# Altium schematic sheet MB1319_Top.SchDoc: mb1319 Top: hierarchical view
size A4; Date: Not used; ApprovedBy: Not used; CheckedBy: Not used; Author: Not used; CompanyName: STMicroelectronics; DrawnBy: Not used; Engineer: Not used; Organization: Not used; Address1: Not used; Address2: Not used; Address3: Not used; Address4: Not used; DocumentNumber: 2; Revision: A-01-P3; SheetNumber: 2; SheetTotal: 8
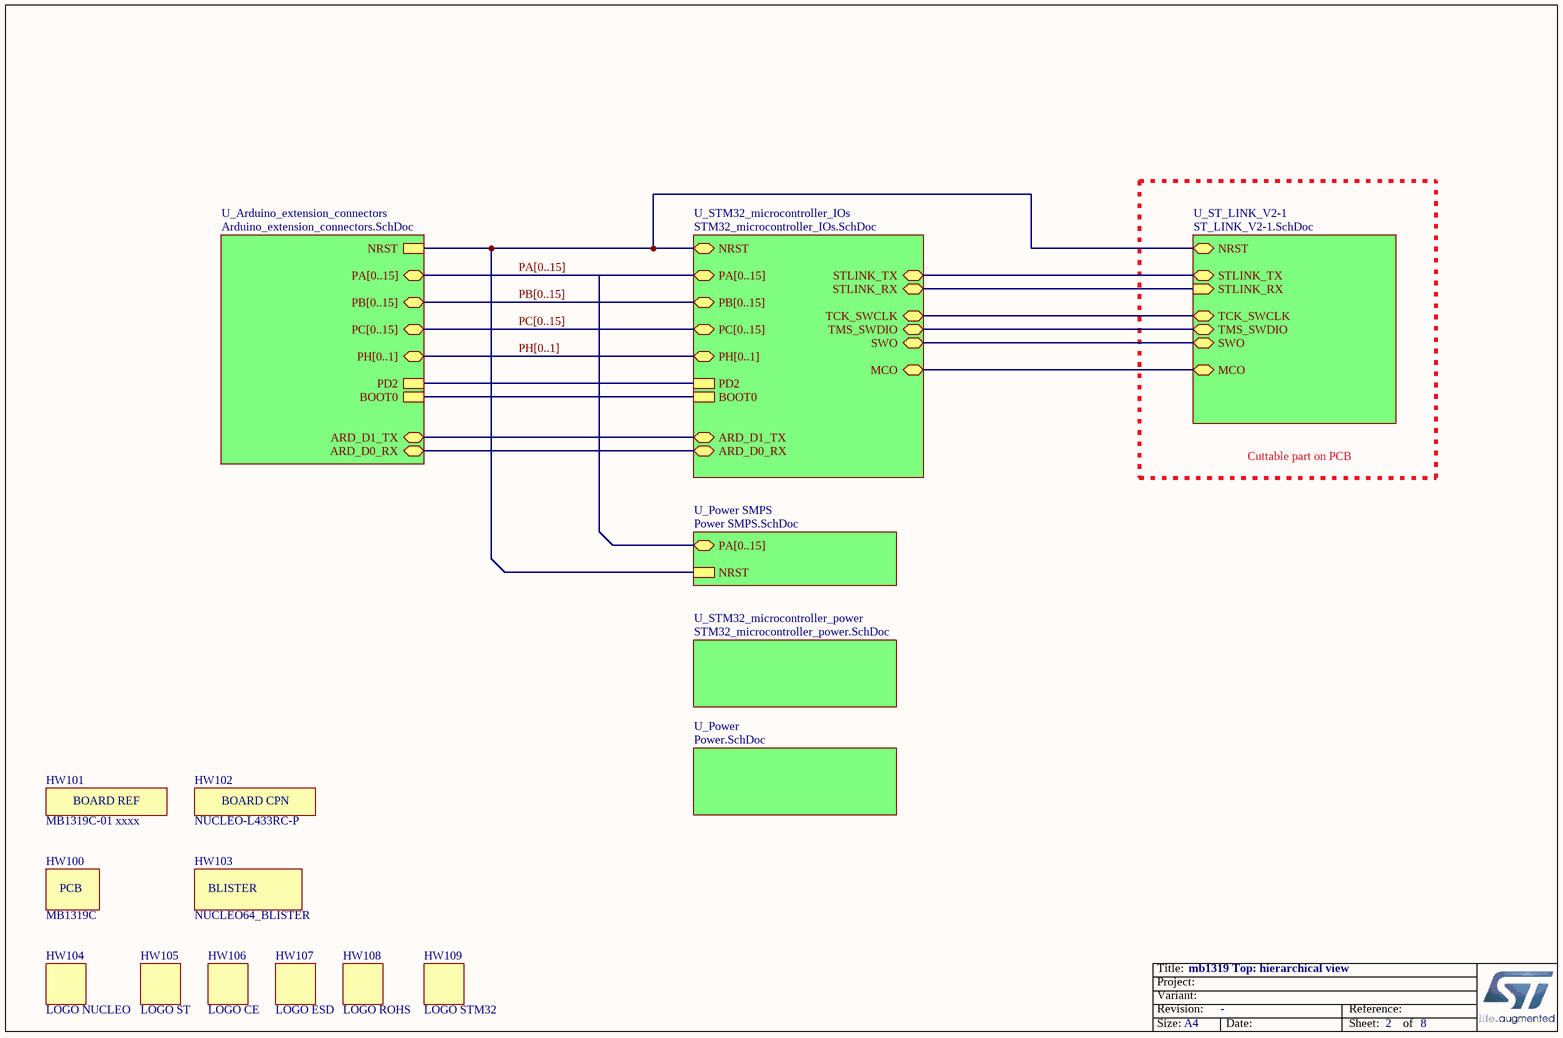
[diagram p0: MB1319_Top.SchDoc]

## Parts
HW100  value MB1319C  (hidden comment: PCB)  (mechanical)
HW101  value MB1319C-01 xxxx  (hidden comment: STICKER_BOARD_REF)  (mechanical)
HW102  value NUCLEO-L433RC-P  (hidden comment: STICKER_BOARD_CPN)  (mechanical)
HW103  value NUCLEO64_BLISTER  [N/A]  (hidden comment: BLISTER)  (mechanical)
HW104  value LOGO NUCLEO  [LOGO_NUCLEO]  (hidden comment: Logo)
HW105  value LOGO ST  [LOGO_STM]  (hidden comment: Logo)
HW106  value LOGO CE  [LOGO_CE]  (hidden comment: Logo)
HW107  value LOGO ESD  [LOGO_MAIN]  (hidden comment: Logo)
HW108  value LOGO ROHS  [LOGO_ROHS]  (hidden comment: Logo)
HW109  value LOGO STM32  [LOGO_STM32]  (hidden comment: Logo)

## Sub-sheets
U_Arduino_extension_connectors = Arduino_extension_connectors.SchDoc: PA[0..15] (bidir), PB[0..15] (bidir), PC[0..15] (bidir), PD2, NRST, BOOT0, PH[0..1] (bidir), ARD_D0_RX, ARD_D1_TX
U_Power = Power.SchDoc: no entries
U_Power SMPS = Power SMPS.SchDoc: PA[0..15] (bidir), NRST
U_ST_LINK_V2-1 = ST_LINK_V2-1.SchDoc: STLINK_TX, TMS_SWDIO, SWO, STLINK_RX (in), MCO, NRST, TCK_SWCLK
U_STM32_microcontroller_IOs = STM32_microcontroller_IOs.SchDoc: PA[0..15] (bidir), PB[0..15] (bidir), PC[0..15] (bidir), PD2, BOOT0, PH[0..1] (bidir), ARD_D0_RX, ARD_D1_TX, NRST, MCO, STLINK_TX, TMS_SWDIO, STLINK_RX, SWO, TCK_SWCLK
U_STM32_microcontroller_power = STM32_microcontroller_power.SchDoc: no entries

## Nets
(unnamed): sheet U_STM32_microcontroller_IOs/PD2, sheet U_Arduino_extension_connectors/PD2
(unnamed): sheet U_STM32_microcontroller_IOs/BOOT0, sheet U_Arduino_extension_connectors/BOOT0  [a separate net that carries the same name]
(unnamed): sheet U_STM32_microcontroller_IOs/ARD_D0_RX, sheet U_Arduino_extension_connectors/ARD_D0_RX  [a separate net that carries the same name]
(unnamed): sheet U_STM32_microcontroller_IOs/ARD_D1_TX, sheet U_Arduino_extension_connectors/ARD_D1_TX  [a separate net that carries the same name]
(unnamed): sheet U_STM32_microcontroller_IOs/NRST, sheet U_Arduino_extension_connectors/NRST, sheet U_Power SMPS/NRST, sheet U_ST_LINK_V2-1/NRST  [a separate net that carries the same name]
(unnamed): sheet U_STM32_microcontroller_IOs/MCO, sheet U_ST_LINK_V2-1/MCO  [a separate net that carries the same name]
(unnamed): sheet U_STM32_microcontroller_IOs/STLINK_TX, sheet U_ST_LINK_V2-1/STLINK_TX  [a separate net that carries the same name]
(unnamed): sheet U_STM32_microcontroller_IOs/TMS_SWDIO, sheet U_ST_LINK_V2-1/TMS_SWDIO  [a separate net that carries the same name]
(unnamed): sheet U_STM32_microcontroller_IOs/STLINK_RX, sheet U_ST_LINK_V2-1/STLINK_RX  [a separate net that carries the same name]
(unnamed): sheet U_STM32_microcontroller_IOs/SWO, sheet U_ST_LINK_V2-1/SWO  [a separate net that carries the same name]
(unnamed): sheet U_STM32_microcontroller_IOs/TCK_SWCLK, sheet U_ST_LINK_V2-1/TCK_SWCLK  [a separate net that carries the same name]

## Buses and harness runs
bus PA[0..15] = sheet U_Arduino_extension_connectors/PA[0..15] = sheet U_Power SMPS/PA[0..15] = sheet U_STM32_microcontroller_IOs/PA[0..15]
bus PB[0..15] = sheet U_Arduino_extension_connectors/PB[0..15] = sheet U_STM32_microcontroller_IOs/PB[0..15]
bus PC[0..15] = sheet U_Arduino_extension_connectors/PC[0..15] = sheet U_STM32_microcontroller_IOs/PC[0..15]
bus PH[0..1] = sheet U_Arduino_extension_connectors/PH[0..1] = sheet U_STM32_microcontroller_IOs/PH[0..1]

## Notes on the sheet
- Cuttable part on PCB

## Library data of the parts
HW100 = MCD-00216: Part_Type: Mechanical; Provided_By: Subcon; Initial_Board_Reference: mb1319
HW101 = MCD-00235: Sticker to mention board reference + serial number; Part_Type: Mechanical; Provided_By: Subcon; Initial_Board_Reference: mb1319
HW102 = MCD-00549: Sticker to mention board CPN code; Part_Type: Mechanical; Provided_By: Subcon; Initial_Board_Reference: mb1319
HW103 = MCD-00037: Part_Type: Mechanical; Provided_By: Subcon; Initial_Board_Reference: mb1274
HW104 = MCD-00636: "NUCLEO" logo footprint for PCB; Part_Type: Mechanical; Initial_Board_Reference: mb1331
HW105 = MCD-00625: "STMicroelectronics" logo footprint for PCB; Part_Type: Mechanical; Initial_Board_Reference: mb1331
HW106 = MCD-00626: "CE" logo footprint for PCB; Part_Type: Mechanical; Initial_Board_Reference: mb1331
HW107 = MCD-00627: "Hand" ESD logo footprint for PCB; Part_Type: Mechanical; Initial_Board_Reference: mb1331
HW108 = MCD-00628: "ROHS" logo footprint for PCB; Part_Type: Mechanical; Initial_Board_Reference: mb1331
HW109 = MCD-00629: "STM32" logo footprint for PCB; Part_Type: Mechanical; Initial_Board_Reference: mb1331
